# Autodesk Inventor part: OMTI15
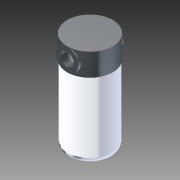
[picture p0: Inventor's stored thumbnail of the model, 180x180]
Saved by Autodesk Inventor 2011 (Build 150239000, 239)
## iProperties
Created: 2013-02
Part Number: OMTI15
Document SubType Name: Modeling
Designer: khramov
Density: 1 g/cm^3
Author: khramov
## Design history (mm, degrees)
derived "OMTI15.iam"
node "Твердое тело1"
node "T05VORI.ipt:1"
node "FRCE-034L.ipt:1"
